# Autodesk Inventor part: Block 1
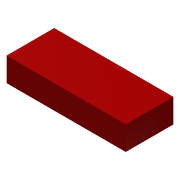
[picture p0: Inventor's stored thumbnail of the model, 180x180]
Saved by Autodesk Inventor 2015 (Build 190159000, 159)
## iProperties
Created: 2020-01
Part Number: Block 1
Material: 一般
Document SubType Name: Modeling
Designer: Kuan_Lun Hsu
Density: 1 g/cm^3
Appearance: 平滑 - 紅色
Author: Kuan_Lun Hsu
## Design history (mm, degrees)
sketch "草圖1"
  geometry: L1 (0, 0)-(15, 0); L2 (15, 0)-(15, 10); L3 (15, 10)-(0, 10); L4 (0, 10)-(0, 0)
  constraints: 8 end point, 2 parallel, 1 horizontal, 1 perpendicular
  dimensions: "d0" = 15 distance of L1.start L1.end; "d1" = 10 distance of L3.end L1.start
extrude "擠出1" new body sketch "草圖1" distance "d2" = 5; taper "d3" = 0 deg
node "實體1"
